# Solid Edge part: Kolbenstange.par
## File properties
Username: bmolnar
Dokumentum tartalom típus: 0
Author: bmolnar
Last saved by: bmolnar
Revision: 87
Sűrűség: 0,000 kg/m^3
Pontosság: 0,990
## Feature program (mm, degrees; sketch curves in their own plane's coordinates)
base feature "unnamed BaseFeature 1"
sketch for "unnamed Protrusion 1" plane through (27.5, 0, 0) normal (1, 0, 0) x-axis (0, -1, 0)
  circle centre (0, 0) radius 25
extrude "unnamed Protrusion 1" add finite 16 along +normal
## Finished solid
Body 1: solid body, 13 faces, 19 edges, 8 vertices.
  Faces by surface: plane 7, cylinder 3, cone 2, torus 1
  Edges by curve: circle 9, line 6, ellipse 2, intersection 2
Bounding box of the edges (mm; curved faces can reach further): 118.500 x 50.000 x 50.000, from (-75, -25, -25) to (43.5, 25, 25).
Cylindrical faces by radius (mm): R4.188 x1, R8 x1, R25 x1
Conical faces (half-angle, radius in mm at the cone's reference point): 45 deg R4.538 x1, 59 deg R2.094 x1
Toroidal faces (ring radius, tube radius in mm): R6.3 r1.7 x1
Planar faces by outward normal: +x 1, +z 1, -x 2, -z 1, oblique 2
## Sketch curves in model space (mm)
circle centre (27.5, 0, 0) radius 25
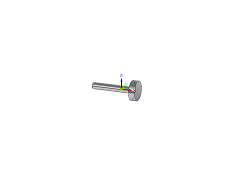
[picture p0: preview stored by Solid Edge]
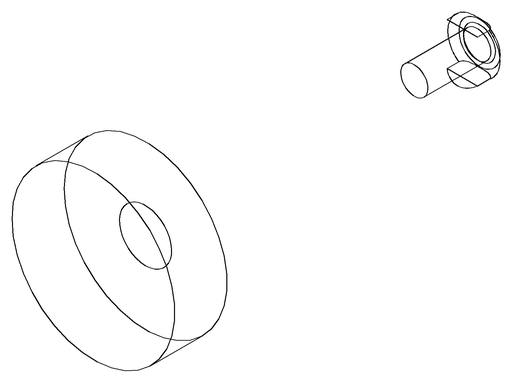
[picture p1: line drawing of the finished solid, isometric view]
